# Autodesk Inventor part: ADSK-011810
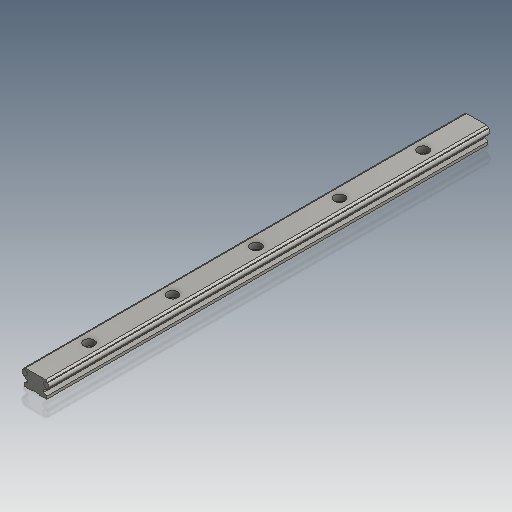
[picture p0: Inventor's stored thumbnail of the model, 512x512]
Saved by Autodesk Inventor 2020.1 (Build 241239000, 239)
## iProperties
Created: 2000-01
Part Number: ADSK-011810
Material: Aluminum
Document SubType Name: Modeling
Designer: glanglot
Density: 2.71 g/cm^3
Appearance: Steel
Mass: 174.196 g
Surface Area: 231.22 cm^2
Volume: 64.2789 cm^3
Control State: 0
Checked Out: False
Master: False
Shininess: 0.0
Length Units: 11269
Angle Units: 11279
Time Units: 11290
Mass Units: 11283
Length Display Precision: 5
Angle Display Precision: 5
Compacted: True
Dimensions: 20x12,2x330 mm
Mass: 0,174 kg
Density: 0.0
Volumn: 0.0
Area: 0.0
PropertySet Name: Model Information
Author: glanglot
Revision Number: -
Title: ADSK-011810
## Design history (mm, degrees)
node "Solide1"
node "Corps solides"
node "Corps surfaciques"
sketch "Sketch1"
  geometry: L1 (-7.5, 12.2)-(7.5, 12.2); L2 (8.5, 0)-(-8.5, 0); L3 (0, 0)-(0, 12.2); L4 (9, 10.732)-(9, 11.334); L5 (-9, 10.732)-(-9, 11.334); L6 (7.5, 12.2)-(9, 11.334); L7 (-7.5, 12.2)-(-9, 11.334); L8 (9, 7.268)-(9, 6.666); L9 (-9, 7.268)-(-9, 6.666); L10 (-9, 6.666)-(-6.193, 5.046); L11 (9, 6.666)-(6.193, 5.046); L12 (8.5, 0)-(8.5, 2); L13 (-8.5, 0)-(-8.5, 2); L14 (8.5, 2)-(6.193, 3.332); L15 (-8.5, 2)-(-6.193, 3.332); L16 (6.193, 3.332)-(6.193, 5.046); L17 (-6.193, 3.332)-(-6.193, 5.046); A1 r 2 centre (8, 9) between (9, 10.732) and (9, 7.268); A2 r 2 centre (-8, 9) between (-9, 10.732) and (-9, 7.268); 3 further points
  constraints: 34 end point, 11 parallel, 5 equal length, 4 point on circle, 3 coincident, 2 centre point, 2 collinear, 2 midpoint, 1 horizontal, 1 perpendicular
  dimensions: "d1" = 15 distance of L1.start L1.end; "d2" = 8 distance from line of point (-8, 9) L3; "d3" = 8 distance from line of point (8, 9) L3 (= d2); "d4" = 9 distance from line of L2 point (8, 9); "d5" = 9 distance from line of point (-8, 9) L2 (= d4); "d6" = 4 diameter of A2; "d7" = 4 diameter of A1 (= d6); "d8" = 12.2 distance between parallel lines of L2 L1; "d9" = 17 distance of L2.start L2.end; "d10" = 9 distance between parallel lines of L5 L3; "d11" = 9 distance between parallel lines of L4 L3 (= d10); "d12" = 150 deg angle of L6 L1; "d13" = 150 deg angle of L7 L1 (= d12); "d16" = 2 distance of L2.start L12.end; "d17" = 12.38668 distance between parallel lines of L17 L16; "d18" = 60 deg angle of L14 L11
node "Extrusion1" dims "d19" = 330, "d20" = 0
node "Extrusion2" dims "d21" = 330.01, "d22" = 0
node "Hole1" dims "d32" = 4.5, "d33" = 8, "d34" = 4.6, "d35" = 60 deg, "d36" = 8, "d37" = 118 deg
node "Extrusion4" dims "d41" = 10, "d42" = 0
sketch "Sketch3"
  geometry: L1 (21.9, -165)-(-3.3, -165) reference; L2 (7.5, 33)-(7.5, -429) reference; 6 further points
  constraints: 5 point on line
  dimensions: "d29" = 0 distance from line of point (7.5, -165) L1; "d30" = 62.5 distance of point (7.5, -227.5) point (7.5, -165); "d31" = 62.5 distance of point (7.5, -290) point (7.5, -227.5); "d44" = 62.5 distance of point (7.5, -40) point (7.5, -102.5); "d45" = 62.5 distance of point (7.5, -102.5) point (7.5, -165)
sketch "Sketch4"
  geometry: L1 (8.5, 0)-(-8.5, 0) reference; L2 (9, 11.334)-(9, 10.732) reference; L3 (-2.789, 0)-(-2.5, 0.5); L4 (-2.5, 0.5)-(2.5, 0.5); L5 (0, 0.5)-(0, 0); L6 (2.5, 0.5)-(2.789, 0)
  constraints: 8 end point, 2 perpendicular, 2 point on line, 1 equal length, 1 midpoint
  dimensions: "d38" = 60 deg angle of L1 L3; "d39" = 0.5 distance between parallel lines of L1 L4; "d40" = 5 distance of L3.end L4.end
